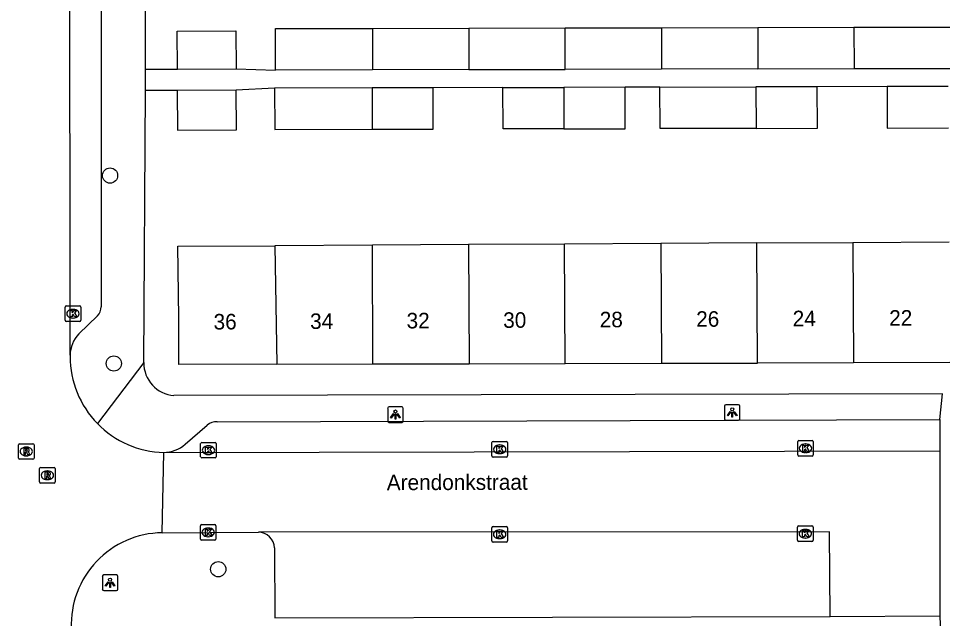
# Model space of a CAD drawing. Extents: x 160732 to 162105, y 387428 to 388479.
# Drawn here: x 161158.3 to 161217.8, y 387897.1 to 387935.7 of the extents above; entities that cross this region are included whole.
import ezdxf

# ---------------------------------------------------------------- set-up
doc = ezdxf.new("R2010")
doc.units = 0
for name, color, linetype in [('IMGEO_Boom', 7, 'Continuous'), ('IMGEO_Kolk', 7, 'Continuous'), ('IMGEO_Lichtpunt', 7, 'Continuous'), ('IMGEO_Openbare_ruimte_label', 7, 'Continuous'), ('IMGEO_Pand', 7, 'Continuous'), ('IMGEO_Pand_nummerreeks', 7, 'Continuous'), ('IMGEO_Rijbaan_lokaal_open', 7, 'Continuous'), ('IMGEO_Rioolput', 7, 'Continuous'), ('IMGEO_Voetpad_open', 7, 'Continuous')]:
    doc.layers.add(name, color=color, linetype=linetype)

msp = doc.modelspace()

# ---------------------------------------------------------------- linework, layer by layer
at = {"layer": 'IMGEO_Boom'}
for centre in [(161164.202, 387925.56), (161164.443, 387913.469), (161171.166, 387900.231)]:
    msp.add_circle(centre, 0.489, dxfattribs=at)
at = {"layer": 'IMGEO_Kolk'}
for p, q in [((161161.312, 387916.247), (161161.312, 387917.099)), ((161161.387, 387917.173), (161162.239, 387917.173)), ((161161.8, 387916.953), (161161.825, 387916.953)), ((161162.313, 387917.099), (161162.313, 387916.247)), ((161161.823, 387916.393), (161161.798, 387916.393)), ((161162.239, 387916.173), (161161.387, 387916.173)), ((161170.034, 387907.467), (161170.034, 387908.319)), ((161170.109, 387908.393), (161170.961, 387908.393)), ((161170.522, 387908.173), (161170.547, 387908.173)), ((161171.035, 387908.319), (161171.035, 387907.467)), ((161188.784, 387907.523), (161188.784, 387908.375)), ((161188.859, 387908.449), (161189.711, 387908.449)), ((161189.272, 387908.229), (161189.297, 387908.229)), ((161189.785, 387908.375), (161189.785, 387907.523)), ((161208.465, 387907.588), (161208.465, 387908.44)), ((161208.54, 387908.514), (161209.392, 387908.514)), ((161208.953, 387908.294), (161208.978, 387908.294)), ((161209.466, 387908.44), (161209.466, 387907.588)), ((161170.545, 387907.613), (161170.52, 387907.613)), ((161189.711, 387907.449), (161188.859, 387907.449)), ((161189.295, 387907.669), (161189.27, 387907.669)), ((161209.392, 387907.514), (161208.54, 387907.514)), ((161208.976, 387907.734), (161208.951, 387907.734)), ((161170.961, 387907.393), (161170.109, 387907.393)), ((161170.019, 387902.175), (161170.019, 387903.027)), ((161170.094, 387903.101), (161170.946, 387903.101)), ((161170.507, 387902.881), (161170.532, 387902.881)), ((161171.02, 387903.027), (161171.02, 387902.175)), ((161188.779, 387902.052), (161188.779, 387902.904)), ((161188.854, 387902.978), (161189.706, 387902.978)), ((161189.267, 387902.758), (161189.292, 387902.758)), ((161189.78, 387902.904), (161189.78, 387902.052)), ((161208.451, 387902.092), (161208.451, 387902.944)), ((161208.526, 387903.018), (161209.378, 387903.018)), ((161208.939, 387902.798), (161208.964, 387902.798)), ((161209.452, 387902.944), (161209.452, 387902.092)), ((161170.946, 387902.101), (161170.094, 387902.101)), ((161170.53, 387902.321), (161170.505, 387902.321)), ((161189.29, 387902.198), (161189.265, 387902.198)), ((161208.962, 387902.238), (161208.937, 387902.238)), ((161189.706, 387901.978), (161188.854, 387901.978)), ((161209.378, 387902.018), (161208.526, 387902.018))]:
    msp.add_line(p, q, dxfattribs=at)
for points in [[(161161.312, 387916.247), (161161.312, 387917.099)], [(161161.387, 387917.173), (161162.239, 387917.173)], [(161162.313, 387917.099), (161162.313, 387916.247)], [(161161.633, 387916.873), (161161.756, 387916.873), (161161.756, 387916.722), (161161.886, 387916.873), (161162.05, 387916.873), (161161.904, 387916.722), (161162.057, 387916.473), (161161.905, 387916.473), (161161.82, 387916.637), (161161.756, 387916.57), (161161.756, 387916.473), (161161.633, 387916.473), (161161.633, 387916.873)], [(161162.239, 387916.173), (161161.387, 387916.173)], [(161170.034, 387907.467), (161170.034, 387908.319)], [(161170.109, 387908.393), (161170.961, 387908.393)], [(161170.355, 387908.093), (161170.478, 387908.093), (161170.478, 387907.942), (161170.608, 387908.093), (161170.772, 387908.093), (161170.626, 387907.942), (161170.779, 387907.693), (161170.627, 387907.693), (161170.542, 387907.857), (161170.478, 387907.79), (161170.478, 387907.693), (161170.355, 387907.693), (161170.355, 387908.093)], [(161171.035, 387908.319), (161171.035, 387907.467)], [(161188.784, 387907.523), (161188.784, 387908.375)], [(161188.859, 387908.449), (161189.711, 387908.449)], [(161189.105, 387908.149), (161189.228, 387908.149), (161189.228, 387907.998), (161189.358, 387908.149), (161189.522, 387908.149), (161189.376, 387907.998), (161189.529, 387907.749), (161189.377, 387907.749), (161189.292, 387907.913), (161189.228, 387907.846), (161189.228, 387907.749), (161189.105, 387907.749), (161189.105, 387908.149)], [(161189.785, 387908.375), (161189.785, 387907.523)], [(161208.465, 387907.588), (161208.465, 387908.44)], [(161208.54, 387908.514), (161209.392, 387908.514)], [(161208.786, 387908.214), (161208.909, 387908.214), (161208.909, 387908.063), (161209.039, 387908.214), (161209.203, 387908.214), (161209.057, 387908.063), (161209.21, 387907.814), (161209.058, 387907.814), (161208.973, 387907.978), (161208.909, 387907.911), (161208.909, 387907.814), (161208.786, 387907.814), (161208.786, 387908.214)], [(161209.466, 387908.44), (161209.466, 387907.588)], [(161189.711, 387907.449), (161188.859, 387907.449)], [(161209.392, 387907.514), (161208.54, 387907.514)], [(161170.961, 387907.393), (161170.109, 387907.393)], [(161170.019, 387902.175), (161170.019, 387903.027)], [(161170.094, 387903.101), (161170.946, 387903.101)], [(161170.34, 387902.801), (161170.463, 387902.801), (161170.463, 387902.65), (161170.593, 387902.801), (161170.757, 387902.801), (161170.611, 387902.65), (161170.764, 387902.401), (161170.612, 387902.401), (161170.527, 387902.565), (161170.463, 387902.498), (161170.463, 387902.401), (161170.34, 387902.401), (161170.34, 387902.801)], [(161171.02, 387903.027), (161171.02, 387902.175)], [(161188.779, 387902.052), (161188.779, 387902.904)], [(161188.854, 387902.978), (161189.706, 387902.978)], [(161189.1, 387902.678), (161189.223, 387902.678), (161189.223, 387902.527), (161189.353, 387902.678), (161189.517, 387902.678), (161189.371, 387902.527), (161189.524, 387902.278), (161189.372, 387902.278), (161189.287, 387902.442), (161189.223, 387902.375), (161189.223, 387902.278), (161189.1, 387902.278), (161189.1, 387902.678)], [(161189.78, 387902.904), (161189.78, 387902.052)], [(161208.451, 387902.092), (161208.451, 387902.944)], [(161208.526, 387903.018), (161209.378, 387903.018)], [(161208.772, 387902.718), (161208.895, 387902.718), (161208.895, 387902.567), (161209.025, 387902.718), (161209.189, 387902.718), (161209.043, 387902.567), (161209.196, 387902.318), (161209.044, 387902.318), (161208.959, 387902.482), (161208.895, 387902.415), (161208.895, 387902.318), (161208.772, 387902.318), (161208.772, 387902.718)], [(161209.452, 387902.944), (161209.452, 387902.092)], [(161170.946, 387902.101), (161170.094, 387902.101)], [(161189.706, 387901.978), (161188.854, 387901.978)], [(161209.378, 387902.018), (161208.526, 387902.018)]]:
    msp.add_lwpolyline(points, dxfattribs=at)
for centre, start, end in [((161161.389, 387917.097), 91.55205, 178.44795), ((161161.389, 387917.097), 91.55205, 178.44795), ((161162.237, 387917.097), 1.55205, 88.44795), ((161162.237, 387917.097), 1.55205, 88.44795), ((161161.389, 387916.249), 181.55205, 268.44795), ((161161.389, 387916.249), 181.55205, 268.44795), ((161162.237, 387916.249), 271.55205, 358.44795), ((161162.237, 387916.249), 271.55205, 358.44795), ((161170.111, 387908.317), 91.55205, 178.44795), ((161170.111, 387908.317), 91.55205, 178.44795), ((161170.959, 387908.317), 1.55205, 88.44795), ((161170.959, 387908.317), 1.55205, 88.44795), ((161188.861, 387908.373), 91.55205, 178.44795), ((161188.861, 387908.373), 91.55205, 178.44795), ((161189.709, 387908.373), 1.55205, 88.44795), ((161189.709, 387908.373), 1.55205, 88.44795), ((161208.542, 387908.438), 91.55205, 178.44795), ((161208.542, 387908.438), 91.55205, 178.44795), ((161209.39, 387908.438), 1.55205, 88.44795), ((161209.39, 387908.438), 1.55205, 88.44795), ((161170.111, 387907.469), 181.55205, 268.44795), ((161170.111, 387907.469), 181.55205, 268.44795), ((161170.959, 387907.469), 271.55205, 358.44795), ((161170.959, 387907.469), 271.55205, 358.44795), ((161188.861, 387907.525), 181.55205, 268.44795), ((161188.861, 387907.525), 181.55205, 268.44795), ((161189.709, 387907.525), 271.55205, 358.44795), ((161189.709, 387907.525), 271.55205, 358.44795), ((161208.542, 387907.59), 181.55205, 268.44795), ((161208.542, 387907.59), 181.55205, 268.44795), ((161209.39, 387907.59), 271.55205, 358.44795), ((161209.39, 387907.59), 271.55205, 358.44795), ((161170.096, 387903.025), 91.55205, 178.44795), ((161170.096, 387903.025), 91.55205, 178.44795), ((161170.944, 387903.025), 1.55205, 88.44795), ((161170.944, 387903.025), 1.55205, 88.44795), ((161188.856, 387902.902), 91.55205, 178.44795), ((161188.856, 387902.902), 91.55205, 178.44795), ((161189.704, 387902.902), 1.55205, 88.44795), ((161189.704, 387902.902), 1.55205, 88.44795), ((161208.528, 387902.942), 91.55205, 178.44795), ((161208.528, 387902.942), 91.55205, 178.44795), ((161209.376, 387902.942), 1.55205, 88.44795), ((161209.376, 387902.942), 1.55205, 88.44795), ((161170.096, 387902.177), 181.55205, 268.44795), ((161170.096, 387902.177), 181.55205, 268.44795), ((161170.944, 387902.177), 271.55205, 358.44795), ((161170.944, 387902.177), 271.55205, 358.44795), ((161208.528, 387902.094), 181.55205, 268.44795), ((161208.528, 387902.094), 181.55205, 268.44795), ((161209.376, 387902.094), 271.55205, 358.44795), ((161209.376, 387902.094), 271.55205, 358.44795), ((161188.856, 387902.054), 181.55205, 268.44795), ((161188.856, 387902.054), 181.55205, 268.44795), ((161189.704, 387902.054), 271.55205, 358.44795), ((161189.704, 387902.054), 271.55205, 358.44795)]:
    msp.add_arc(centre, 0.0765, start, end, dxfattribs=at)
for centre, major_axis, ratio, start_param, end_param in [((161161.799, 387916.673), (-0.387, 0.002), 0.722429, 4.712389, 7.853982), ((161161.824, 387916.673), (-0.39, 0.002), 0.717154, 1.570796, 4.712389), ((161170.521, 387907.893), (-0.387, 0.002), 0.722429, 4.712389, 7.853982), ((161170.546, 387907.893), (-0.39, 0.002), 0.717154, 1.570796, 4.712389), ((161189.271, 387907.949), (-0.387, 0.002), 0.722429, 4.712389, 7.853982), ((161189.296, 387907.949), (-0.39, 0.002), 0.717154, 1.570796, 4.712389), ((161208.952, 387908.014), (-0.387, 0.002), 0.722429, 4.712389, 7.853982), ((161208.977, 387908.014), (-0.39, 0.002), 0.717154, 1.570796, 4.712389), ((161170.506, 387902.601), (-0.387, 0.002), 0.722429, 4.712389, 7.853982), ((161170.531, 387902.601), (-0.39, 0.002), 0.717154, 1.570796, 4.712389), ((161189.266, 387902.478), (-0.387, 0.002), 0.722429, 4.712389, 7.853982), ((161189.291, 387902.478), (-0.39, 0.002), 0.717154, 1.570796, 4.712389), ((161208.938, 387902.518), (-0.387, 0.002), 0.722429, 4.712389, 7.853982), ((161208.963, 387902.518), (-0.39, 0.002), 0.717154, 1.570796, 4.712389)]:
    msp.add_ellipse(centre, major_axis=major_axis, ratio=ratio, start_param=start_param, end_param=end_param, dxfattribs=at)
at = {"layer": 'IMGEO_Lichtpunt'}
for p, q in [((161182.071, 387910.583), (161182.071, 387909.776)), ((161182.071, 387910.583), (161182.071, 387909.776)), ((161182.973, 387910.678), (161182.165, 387910.678)), ((161182.973, 387910.678), (161182.165, 387910.678)), ((161183.067, 387909.776), (161183.067, 387910.583)), ((161183.067, 387909.776), (161183.067, 387910.583)), ((161203.75, 387910.723), (161203.75, 387909.916)), ((161203.75, 387910.723), (161203.75, 387909.916)), ((161204.652, 387910.818), (161203.844, 387910.818)), ((161204.652, 387910.818), (161203.844, 387910.818)), ((161204.746, 387909.916), (161204.746, 387910.723)), ((161204.746, 387909.916), (161204.746, 387910.723)), ((161203.844, 387909.822), (161204.652, 387909.822)), ((161203.844, 387909.822), (161204.652, 387909.822)), ((161182.165, 387909.682), (161182.973, 387909.682)), ((161182.165, 387909.682), (161182.973, 387909.682)), ((161163.705, 387899.766), (161163.705, 387898.959)), ((161163.705, 387899.766), (161163.705, 387898.959)), ((161164.607, 387899.861), (161163.799, 387899.861)), ((161164.607, 387899.861), (161163.799, 387899.861)), ((161164.701, 387898.959), (161164.701, 387899.766)), ((161164.701, 387898.959), (161164.701, 387899.766)), ((161163.799, 387898.865), (161164.607, 387898.865)), ((161163.799, 387898.865), (161164.607, 387898.865))]:
    msp.add_line(p, q, dxfattribs=at)
for points in [[(161182.445, 387910.247), (161182.484, 387910.219), (161182.296, 387909.957), (161182.258, 387909.984), (161182.445, 387910.247)], [(161182.547, 387910.199), (161182.594, 387910.199), (161182.594, 387909.877), (161182.547, 387909.877), (161182.547, 387910.199)], [(161182.657, 387910.219), (161182.695, 387910.246), (161182.882, 387909.984), (161182.843, 387909.956), (161182.657, 387910.219)], [(161204.124, 387910.387), (161204.163, 387910.359), (161203.975, 387910.097), (161203.937, 387910.124), (161204.124, 387910.387)], [(161204.226, 387910.339), (161204.273, 387910.339), (161204.273, 387910.017), (161204.226, 387910.017), (161204.226, 387910.339)], [(161204.336, 387910.359), (161204.374, 387910.386), (161204.561, 387910.124), (161204.522, 387910.096), (161204.336, 387910.359)], [(161164.079, 387899.43), (161164.118, 387899.402), (161163.93, 387899.14), (161163.892, 387899.167), (161164.079, 387899.43)], [(161164.181, 387899.382), (161164.228, 387899.382), (161164.228, 387899.06), (161164.181, 387899.06), (161164.181, 387899.382)], [(161164.291, 387899.402), (161164.329, 387899.429), (161164.516, 387899.167), (161164.477, 387899.139), (161164.291, 387899.402)]]:
    msp.add_lwpolyline(points, dxfattribs=at)
for centre in [(161182.57, 387910.381), (161204.249, 387910.521), (161164.204, 387899.564)]:
    msp.add_circle(centre, 0.0994, dxfattribs=at)
for centre, start, end in [((161182.165, 387910.583), 90, 180), ((161182.165, 387910.583), 90, 180), ((161182.973, 387910.583), 0, 90), ((161182.973, 387910.583), 0, 90), ((161203.844, 387910.723), 90, 180), ((161203.844, 387910.723), 90, 180), ((161204.652, 387910.723), 0, 90), ((161204.652, 387910.723), 0, 90), ((161203.844, 387909.916), 180, 270), ((161203.844, 387909.916), 180, 270), ((161204.652, 387909.916), 270, 0), ((161204.652, 387909.916), 270, 360), ((161182.165, 387909.776), 180, 270), ((161182.165, 387909.776), 180, 270), ((161182.973, 387909.776), 270, 0), ((161182.973, 387909.776), 270, 360), ((161163.799, 387899.766), 90, 180), ((161163.799, 387899.766), 90, 180), ((161164.607, 387899.766), 0, 90), ((161164.607, 387899.766), 0, 90), ((161163.799, 387898.959), 180, 270), ((161163.799, 387898.959), 180, 270), ((161164.607, 387898.959), 270, 0), ((161164.607, 387898.959), 270, 360)]:
    msp.add_arc(centre, 0.0946, start, end, dxfattribs=at)
at = {"layer": 'IMGEO_Pand'}
for points in [[(161168.537, 387932.413), (161168.523, 387934.857), (161172.306, 387934.879), (161172.319, 387932.435)], [(161174.851, 387932.35), (161174.845, 387935.015), (161181.088, 387935.03)], [(161181.088, 387935.03), (161187.287, 387935.044)], [(161181.088, 387935.03), (161181.102, 387932.365)], [(161187.287, 387935.044), (161193.488, 387935.059)], [(161187.287, 387935.044), (161187.301, 387932.379)], [(161193.488, 387935.059), (161199.687, 387935.074)], [(161193.503, 387932.394), (161193.488, 387935.059)], [(161199.687, 387935.074), (161205.886, 387935.089)], [(161199.687, 387935.074), (161199.702, 387932.409)], [(161205.886, 387935.089), (161212.085, 387935.103)], [(161205.886, 387935.089), (161205.901, 387932.424)], [(161212.085, 387935.103), (161218.284, 387935.118)], [(161212.085, 387935.103), (161212.1, 387932.439)], [(161168.537, 387932.413), (161172.319, 387932.435)], [(161205.901, 387932.424), (161199.702, 387932.409)], [(161205.901, 387932.424), (161212.1, 387932.439)], [(161212.1, 387932.439), (161218.299, 387932.453)], [(161181.102, 387932.365), (161174.851, 387932.35)], [(161187.301, 387932.379), (161181.102, 387932.365)], [(161187.301, 387932.379), (161193.503, 387932.394)], [(161199.702, 387932.409), (161193.503, 387932.394)], [(161189.491, 387931.222), (161193.4, 387931.231)], [(161197.347, 387931.241), (161193.4, 387931.231)], [(161193.4, 387931.231), (161193.415, 387928.566)], [(161193.415, 387928.566), (161197.353, 387928.576), (161197.347, 387931.241)], [(161199.588, 387931.246), (161205.775, 387931.261)], [(161205.79, 387928.596), (161199.603, 387928.581), (161199.588, 387931.246)], [(161209.722, 387931.271), (161205.775, 387931.261)], [(161205.775, 387931.261), (161205.79, 387928.596)], [(161205.79, 387928.596), (161209.728, 387928.606), (161209.722, 387931.271)], [(161218.151, 387931.29), (161214.222, 387931.281)], [(161214.222, 387931.281), (161214.228, 387928.616), (161218.166, 387928.625)], [(161168.524, 387931.038), (161168.538, 387928.479), (161172.331, 387928.501), (161172.317, 387931.06)], [(161172.317, 387931.06), (161168.524, 387931.038)], [(161181.069, 387931.202), (161174.793, 387931.187)], [(161174.793, 387931.187), (161174.8, 387928.522), (161181.077, 387928.537)], [(161184.991, 387931.212), (161181.069, 387931.202)], [(161181.069, 387931.202), (161181.077, 387928.537)], [(161181.077, 387928.537), (161184.997, 387928.547), (161184.991, 387931.212)], [(161193.415, 387928.566), (161189.497, 387928.557), (161189.491, 387931.222)], [(161187.279, 387921.118), (161181.101, 387921.083)], [(161193.457, 387921.152), (161187.279, 387921.118)], [(161187.279, 387921.118), (161187.312, 387913.454)], [(161199.645, 387921.187), (161193.457, 387921.152)], [(161193.501, 387913.469), (161193.457, 387921.152)], [(161205.832, 387921.221), (161199.645, 387921.187)], [(161199.645, 387921.187), (161199.689, 387913.483)], [(161205.832, 387921.221), (161212.02, 387921.256)], [(161205.876, 387913.498), (161205.832, 387921.221)], [(161212.02, 387921.256), (161218.208, 387921.291)], [(161212.02, 387921.256), (161212.064, 387913.513)], [(161174.934, 387913.425), (161168.63, 387913.41), (161168.623, 387916.41), (161168.557, 387921.013), (161174.813, 387921.048)], [(161181.101, 387921.083), (161174.813, 387921.048)], [(161174.813, 387921.048), (161174.934, 387913.425)], [(161181.125, 387913.44), (161181.101, 387921.083)], [(161174.934, 387913.425), (161181.125, 387913.44)], [(161181.125, 387913.44), (161187.312, 387913.454)], [(161187.312, 387913.454), (161193.501, 387913.469)], [(161193.501, 387913.469), (161199.689, 387913.483)], [(161199.689, 387913.483), (161205.876, 387913.498)], [(161212.064, 387913.513), (161205.876, 387913.498)], [(161218.252, 387913.527), (161212.064, 387913.513)]]:
    msp.add_lwpolyline(points, dxfattribs=at)
at = {"layer": 'IMGEO_Rijbaan_lokaal_open'}
for points in [[(161161.627, 387913.997), (161161.618, 387942.56)], [(161161.627, 387913.997), (161161.627, 387913.926)], [(161167.547, 387902.579), (161167.655, 387907.748)], [(161167.655, 387907.748), (161217.608, 387907.852)], [(161217.608, 387907.852), (161217.603, 387897.233)], [(161167.547, 387902.579), (161173.756, 387902.617)], [(161210.557, 387897.189), (161210.509, 387902.644), (161173.756, 387902.617)], [(161210.557, 387897.189), (161217.603, 387897.233)]]:
    msp.add_lwpolyline(points, dxfattribs=at)
for centre, radius, start, end in [((161167.81, 387913.926), 6.183, 180.00461, 224.2741), ((161167.807, 387913.928), 6.182, 224.30817, 268.59077), ((161167.632, 387896.646), 5.934, 90.8174, 182.16081)]:
    msp.add_arc(centre, radius, start, end, dxfattribs=at)
at = {"layer": 'IMGEO_Rioolput'}
for p, q in [((161158.307, 387907.38), (161158.307, 387908.232)), ((161158.382, 387908.306), (161159.234, 387908.306)), ((161158.795, 387908.086), (161158.82, 387908.086)), ((161159.308, 387908.232), (161159.308, 387907.38)), ((161158.818, 387907.526), (161158.793, 387907.526)), ((161159.234, 387907.306), (161158.382, 387907.306)), ((161159.667, 387905.85), (161159.667, 387906.702)), ((161159.742, 387906.776), (161160.594, 387906.776)), ((161160.155, 387906.556), (161160.18, 387906.556)), ((161160.668, 387906.702), (161160.668, 387905.85)), ((161160.594, 387905.776), (161159.742, 387905.776)), ((161160.178, 387905.996), (161160.153, 387905.996))]:
    msp.add_line(p, q, dxfattribs=at)
for points in [[(161158.307, 387907.38), (161158.307, 387908.232)], [(161158.382, 387908.306), (161159.234, 387908.306)], [(161159.308, 387908.232), (161159.308, 387907.38)], [(161158.896, 387908.004), (161158.644, 387908.006), (161158.644, 387907.606)], [(161158.644, 387907.606), (161158.768, 387907.606), (161158.768, 387907.768), (161158.779, 387907.768)], [(161158.822, 387907.925), (161158.768, 387907.925), (161158.768, 387907.844)], [(161158.768, 387907.844), (161158.82, 387907.844)], [(161158.826, 387907.739), (161158.897, 387907.606), (161159.037, 387907.606), (161158.972, 387907.732)], [(161159.234, 387907.306), (161158.382, 387907.306)], [(161159.667, 387905.85), (161159.667, 387906.702)], [(161159.742, 387906.776), (161160.594, 387906.776)], [(161160.256, 387906.474), (161160.004, 387906.476), (161160.004, 387906.076)], [(161160.182, 387906.395), (161160.128, 387906.395), (161160.128, 387906.314)], [(161160.128, 387906.314), (161160.18, 387906.314)], [(161160.668, 387906.702), (161160.668, 387905.85)], [(161160.594, 387905.776), (161159.742, 387905.776)], [(161160.004, 387906.076), (161160.128, 387906.076), (161160.128, 387906.238), (161160.139, 387906.238)], [(161160.186, 387906.209), (161160.257, 387906.076), (161160.397, 387906.076), (161160.332, 387906.202)]]:
    msp.add_lwpolyline(points, dxfattribs=at)
for centre, radius, start, end in [((161158.384, 387908.23), 0.0765, 91.55205, 178.44795), ((161158.384, 387908.23), 0.0765, 91.55205, 178.44795), ((161159.232, 387908.23), 0.0765, 1.55205, 88.44795), ((161159.232, 387908.23), 0.0765, 1.55205, 88.44795), ((161158.778, 387907.715), 0.0533, 26.02933, 88.69889), ((161158.804, 387908.033), 0.19, 274.7715, 282.96867), ((161158.828, 387907.829), 0.0964, 77.00612, 93.18647), ((161158.842, 387907.886), 0.0378, 276.66336, 79.67722), ((161158.895, 387907.894), 0.109, 350.36119, 89.41601), ((161158.893, 387907.894), 0.112, 277.58423, 350.98172), ((161158.877, 387907.679), 0.108, 29.51342, 73.79051), ((161158.384, 387907.382), 0.0765, 181.55205, 268.44795), ((161158.384, 387907.382), 0.0765, 181.55205, 268.44795), ((161159.232, 387907.382), 0.0765, 271.55205, 358.44795), ((161159.232, 387907.382), 0.0765, 271.55205, 358.44795), ((161159.744, 387906.7), 0.0765, 91.55205, 178.44795), ((161159.744, 387906.7), 0.0765, 91.55205, 178.44795), ((161160.164, 387906.503), 0.19, 274.7715, 282.96867), ((161160.188, 387906.299), 0.0964, 77.00612, 93.18647), ((161160.202, 387906.356), 0.0378, 276.66336, 79.67722), ((161160.255, 387906.364), 0.109, 350.36119, 89.41601), ((161160.253, 387906.364), 0.112, 277.58423, 350.98172), ((161160.237, 387906.149), 0.108, 29.51342, 73.79051), ((161160.592, 387906.7), 0.0765, 1.55205, 88.44795), ((161160.592, 387906.7), 0.0765, 1.55205, 88.44795), ((161159.744, 387905.852), 0.0765, 181.55205, 268.44795), ((161159.744, 387905.852), 0.0765, 181.55205, 268.44795), ((161160.138, 387906.185), 0.0533, 26.02933, 88.69889), ((161160.592, 387905.852), 0.0765, 271.55205, 358.44795), ((161160.592, 387905.852), 0.0765, 271.55205, 358.44795)]:
    msp.add_arc(centre, radius, start, end, dxfattribs=at)
for centre, major_axis, ratio, start_param, end_param in [((161158.794, 387907.806), (-0.387, 0.002), 0.722429, 4.712389, 7.853982), ((161158.819, 387907.806), (-0.39, 0.002), 0.717154, 1.570796, 4.712389), ((161160.154, 387906.276), (-0.387, 0.002), 0.722429, 4.712389, 7.853982), ((161160.179, 387906.276), (-0.39, 0.002), 0.717154, 1.570796, 4.712389)]:
    msp.add_ellipse(centre, major_axis=major_axis, ratio=ratio, start_param=start_param, end_param=end_param, dxfattribs=at)
at = {"layer": 'IMGEO_Voetpad_open'}
for points in [[(161166.481, 387932.401), (161166.474, 387942.759), (161166.323, 387942.76), (161166.352, 387950.318)], [(161161.599, 387947.756), (161163.631, 387947.771), (161163.64, 387917.113)], [(161172.319, 387932.435), (161174.851, 387932.35)], [(161166.475, 387931.026), (161166.481, 387932.401)], [(161166.481, 387932.401), (161168.537, 387932.413)], [(161199.588, 387931.246), (161197.347, 387931.241)], [(161214.222, 387931.281), (161209.722, 387931.271)], [(161166.372, 387913.524), (161166.475, 387931.026)], [(161168.524, 387931.038), (161166.475, 387931.026)], [(161174.793, 387931.187), (161172.317, 387931.06)], [(161189.491, 387931.222), (161184.991, 387931.212)], [(161163.388, 387916.538), (161162.191, 387915.375)], [(161166.372, 387913.524), (161163.383, 387909.61)], [(161217.792, 387911.526), (161168.317, 387911.418)], [(161217.608, 387909.867), (161217.792, 387911.526)], [(161171.099, 387909.706), (161217.608, 387909.867)], [(161217.608, 387909.867), (161217.608, 387907.852)], [(161169.046, 387908.272), (161170.451, 387909.51)], [(161174.787, 387901.608), (161174.805, 387897.107), (161210.557, 387897.189)], [(161217.603, 387897.233), (161217.776, 387892.744)]]:
    msp.add_lwpolyline(points, dxfattribs=at)
for centre, radius, start, end in [((161162.792, 387917.142), 0.848, 314.61793, 358.05015), ((161163.671, 387913.965), 2.044, 136.38312, 179.0994), ((161168.454, 387913.495), 2.082, 179.21381, 266.23434), ((161170.998, 387908.872), 0.841, 83.08234, 130.57555), ((161167.62, 387909.949), 2.201, 270.9075, 310.37603), ((161173.731, 387901.56), 1.057, 2.59661, 88.63913)]:
    msp.add_arc(centre, radius, start, end, dxfattribs=at)

# ---------------------------------------------------------------- texts
at = {"layer": 'IMGEO_Openbare_ruimte_label'}
msp.add_text('Arendonkstraat', height=1, rotation=0.17189, dxfattribs=at).set_placement((161182.015, 387905.316))
at = {"layer": 'IMGEO_Pand_nummerreeks'}
for s, p in [('36', (161170.867, 387915.654)), ('34', (161177.08, 387915.689)), ('32', (161183.29, 387915.724)), ('30', (161189.509, 387915.759)), ('28', (161195.722, 387915.793)), ('26', (161201.931, 387915.828)), ('24', (161208.144, 387915.863)), ('22', (161214.354, 387915.898))]:
    msp.add_text(s, height=1, rotation=0.32047, dxfattribs=at).set_placement(p)

doc.saveas('drawing.dxf')
